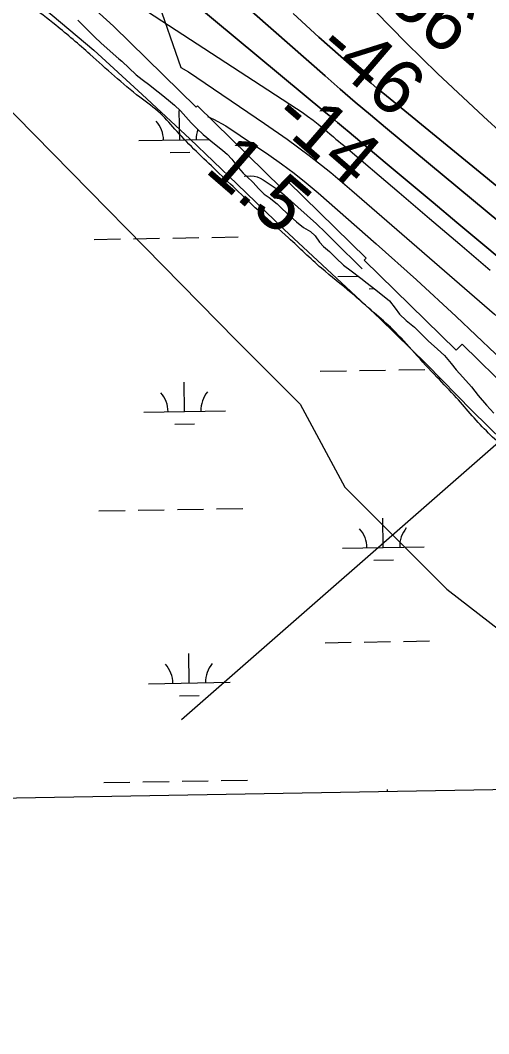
# Model space of a CAD drawing. Extents: x 3892998 to 3931244, y 278583 to 304547.
# Drawn here: x 3913942 to 3914515, y 284015 to 285257 of the extents above; entities that cross this region are included whole.
import ezdxf

# ---------------------------------------------------------------- set-up
doc = ezdxf.new("R2010")
doc.units = 0
for name, color, linetype in [('V-GRID-FRAM', 7, 'Continuous'), ('V-RIVR-EDGE', 7, 'Continuous'), ('V-RIVR-RANG', 7, 'Continuous'), ('V-RRAP-FSHR', 7, 'Continuous'), ('V-RRAP-RVMT', 7, 'Continuous'), ('V-SITE-VEGE', 7, 'Continuous'), ('V-TOPO-DPTH', 7, 'Continuous'), ('V-TOPO-MAJR', 7, 'Continuous'), ('V-TOPO-MINR', 7, 'Continuous'), ('V-TOPO-WATR', 7, 'Continuous'), ('V-WETL-SWMP', 7, 'Continuous')]:
    doc.layers.add(name, color=color, linetype=linetype)

msp = doc.modelspace()

# ---------------------------------------------------------------- linework, layer by layer
at = {"layer": 'V-GRID-FRAM'}
msp.add_lwpolyline([(3896958.4, 302195.2), (3928823.6, 302746.7), (3929146.3, 284567.1), (3897265.1, 284015.2), (3896958.4, 302195.2)], dxfattribs=at)
at = {"layer": 'V-RIVR-EDGE'}
msp.add_spline([(3914993.8, 284322.8), (3914968.3, 284342.8), (3914920.3, 284384.2), (3914880.1, 284418.3), (3914821, 284468.4), (3914766.3, 284522), (3914701.3, 284583.8), (3914632.5, 284646.6), (3914610.2, 284666.6), (3914581.2, 284690), (3914556, 284713.8), (3914514.8, 284750.9), (3914475.6, 284794.2), (3914451.8, 284819.5), (3914424.2, 284849.2), (3914397.6, 284877.9), (3914374.8, 284898.3), (3914346.7, 284922.7), (3914310.3, 284952.9), (3914270.1, 284989.9), (3914236.2, 285020.6), (3914181.9, 285072.2), (3914133.5, 285120.4), (3914113.2, 285142.3), (3914088, 285162.3), (3914026.9, 285214.9), (3913985.2, 285250.4), (3913923.7, 285300.6), (3913885.4, 285338.6), (3913828.2, 285387.3), (3913773, 285434), (3913712.4, 285486.1), (3913642.6, 285542.2), (3913620.3, 285557.3), (3913592.7, 285572.4), (3913575.7, 285582.2), (3913557.7, 285592.9), (3913537.8, 285602.2), (3913513.1, 285610), (3913480.6, 285617.8), (3913452, 285625.7), (3913431.6, 285624.8), (3913416.5, 285623.3), (3913398.5, 285612.2), (3913380, 285595.7), (3913368.8, 285578.8), (3913361, 285558.9), (3913353.2, 285538.5), (3913346.8, 285528.8), (3913334.6, 285516.7), (3913321, 285502.7), (3913315.6, 285483.2), (3913310.2, 285462.9), (3913309.7, 285439.5), (3913307.1, 285396.3), (3913306.6, 285384.7), (3913313.4, 285371.6), (3913315.8, 285356.5), (3913316.7, 285340.9), (3913314.3, 285325.4), (3913310.3, 285313.3), (3913303, 285304.1), (3913292.8, 285303.6), (3913281.2, 285304.1), (3913270.5, 285307.6), (3913265.7, 285307.6), (3913263.2, 285304.2), (3913266.1, 285298.3), (3913272.4, 285295.4), (3913294.3, 285287.6), (3913301.5, 285287.6), (3913314.2, 285288), (3913321.9, 285287), (3913325.8, 285283.6), (3913329.7, 285280.7), (3913333.5, 285262.7), (3913334.5, 285242.3), (3913329, 285204.5), (3913324.1, 285171), (3913320.6, 285146.2), (3913319.1, 285121.9), (3913321, 285110.3), (3913321, 285095.7), (3913319.5, 285083.6), (3913315.1, 285061.2), (3913296, 285013.2), (3913271.1, 284963.7), (3913263.3, 284941.4), (3913260.8, 284917.1), (3913261.7, 284891.9), (3913265, 284860.3), (3913263.5, 284819)], degree=3, dxfattribs=at)
at = {"layer": 'V-RIVR-RANG'}
msp.add_line((3914138.9, 284400), (3915102.1, 285243.1), dxfattribs=at)
at = {"layer": 'V-RRAP-FSHR'}
msp.add_lwpolyline([(3913910.3, 285324), (3913970.6, 285271.5), (3914031.8, 285219.8), (3914090.7, 285165.8), (3914149.3, 285111.3), (3914207, 285055.9), (3914264.5, 285000.3), (3914323.2, 284945.9), (3914381.8, 284891.4), (3914438.9, 284835.5), (3914494.9, 284778.3), (3914551.9, 284722.2), (3914610.7, 284667.3), (3914668.9, 284613.7), (3914727.9, 284559.7), (3914786.2, 284504.2), (3914845.3, 284450.4), (3914906.8, 284399.2), (3914969.5, 284349.5)], dxfattribs=at)
at = {"layer": 'V-RRAP-RVMT'}
for p, q in [((3914055.6, 285249.4), (3913968.2, 285329.4)), ((3914157, 285150), (3914055.6, 285249.4)), ((3914158.6, 285151.6), (3914157, 285150)), ((3914261.5, 285050.7), (3914158.6, 285151.6)), ((3914269.5, 285058.8), (3914261.5, 285050.7)), ((3914364.9, 284965.2), (3914269.5, 285058.8)), ((3914362.6, 284962.9), (3914364.9, 284965.2)), ((3914475.1, 284852.4), (3914362.6, 284962.9)), ((3914482.5, 284859.9), (3914475.1, 284852.4)), ((3914588.9, 284755.5), (3914482.5, 284859.9))]:
    msp.add_line(p, q, dxfattribs=at)
at = {"layer": 'V-SITE-VEGE'}
for p, q in [((3913753.7, 285324.9), (3914206.3, 284864.3)), ((3914206.3, 284864.3), (3914284.3, 284786.2)), ((3914284.3, 284786.2), (3914338.9, 284684.7)), ((3914338.9, 284684.7), (3914463.8, 284559.8)), ((3914463.8, 284559.8), (3914674.5, 284395.9)), ((3914838.2, 284319.4), (3913226.8, 284291.5))]:
    msp.add_line(p, q, dxfattribs=at)
at = {"layer": 'V-TOPO-DPTH'}
msp.add_line((3914093.5, 285327.6), (3914138, 285198.6), dxfattribs=at)
for points in [[(3915362.5, 284328.5), (3915042.9, 284585.9), (3915025, 284600.3), (3915007.3, 284614.7), (3914989.5, 284629.2), (3914971.8, 284643.7), (3914847.8, 284745.4), (3914768.2, 284810.9), (3914688.7, 284876.4), (3914609.2, 284942.1), (3914529.9, 285007.9), (3914388.8, 285125.2), (3914370.2, 285140.7), (3914351.6, 285156.4), (3914333.3, 285172.3), (3914315, 285188.3), (3914118.6, 285361.1), (3914060.1, 285412.9), (3914001.9, 285464.9), (3913944, 285517.3), (3913886.3, 285570)], [(3915362.5, 284328.5), (3915042.9, 284585.9), (3915025, 284600.3), (3915007.3, 284614.7), (3914989.5, 284629.2), (3914971.8, 284643.7), (3914847.8, 284745.4), (3914768.2, 284810.9), (3914688.7, 284876.4), (3914609.2, 284942.1), (3914529.9, 285007.9), (3914388.8, 285125.2), (3914370.2, 285140.7), (3914351.6, 285156.4), (3914333.3, 285172.3), (3914315, 285188.3), (3914118.6, 285361.1), (3914060.1, 285412.9), (3914018.1, 285450.4)], [(3914018.1, 285450.4), (3914093.5, 285327.6), (3914122.5, 285304.2), (3914315.7, 285143.3), (3914322.9, 285137.3), (3914330, 285131.3), (3914337.2, 285125.3), (3914344.4, 285119.3), (3914388.5, 285082.3), (3914417.8, 285057.7), (3914447.1, 285033.2), (3914476.3, 285008.7), (3914505.6, 284984.2), (3914971.2, 284594.7), (3914977.3, 284589.6), (3914983.4, 284584.5), (3914989.5, 284579.4), (3914995.6, 284574.3), (3915054.8, 284524.2), (3915090.5, 284494), (3915126.2, 284463.8), (3915161.8, 284433.6), (3915197.5, 284403.4), (3915287.3, 284327.2)], [(3915287.3, 284327.2), (3915197.5, 284403.4), (3915161.8, 284433.6), (3915126.2, 284463.8), (3915090.5, 284494), (3915054.8, 284524.2), (3914995.6, 284574.3), (3914989.5, 284579.4), (3914983.4, 284584.5), (3914977.3, 284589.6), (3914971.2, 284594.7), (3914505.6, 284984.2), (3914476.3, 285008.7), (3914447.1, 285033.2), (3914417.8, 285057.7), (3914388.5, 285082.3), (3914344.4, 285119.3), (3914337.2, 285125.3), (3914330, 285131.3), (3914322.9, 285137.3), (3914315.7, 285143.3), (3914122.5, 285304.2), (3914093.5, 285327.6)], [(3914275.6, 285264.8), (3914307.1, 285235.9), (3914357.6, 285191.2), (3914364.4, 285185.2), (3914371.3, 285179.3), (3914378.3, 285173.4), (3914385.3, 285167.6), (3914903.1, 284743.7), (3914923.9, 284726.6), (3914944.8, 284709.6), (3914965.7, 284692.5), (3914986.6, 284675.5), (3915019.4, 284648.7), (3915023.9, 284645.1), (3915028.4, 284641.4), (3915032.9, 284637.8), (3915037.4, 284634.1), (3915111.1, 284574.5), (3915152.4, 284541), (3915193.7, 284507.5), (3915235, 284473.9), (3915276.2, 284440.4), (3915412.3, 284329.4)], [(3917760.4, 284370), (3915412.3, 284329.4), (3915276.2, 284440.4), (3915235, 284473.9), (3915193.7, 284507.5), (3915152.4, 284541), (3915111.1, 284574.5), (3915037.4, 284634.1), (3915032.9, 284637.8), (3915028.4, 284641.4), (3915023.9, 284645.1), (3915019.4, 284648.7), (3914986.6, 284675.5), (3914965.7, 284692.5), (3914944.8, 284709.6), (3914923.9, 284726.6), (3914903.1, 284743.7), (3914385.3, 285167.6), (3914378.3, 285173.4), (3914371.3, 285179.3), (3914364.4, 285185.2), (3914357.6, 285191.2), (3914307.1, 285235.9), (3914275.6, 285264.8)], [(3914138, 285198.6), (3914147.7, 285193.3), (3914240.8, 285130.2), (3914268.3, 285110.9), (3914295.4, 285090.8), (3914321.7, 285069.9), (3914347.5, 285048.2), (3914522.2, 284896.4), (3914591.8, 284835.1), (3914660.9, 284773.1), (3914729.2, 284710.2), (3914796.8, 284646.7), (3914882, 284565.6), (3914906.8, 284542.3), (3914931.8, 284519.1), (3914957, 284496.2), (3914982.3, 284473.5), (3915042.1, 284420.6), (3915097.8, 284372), (3915152.9, 284324.9)]]:
    msp.add_lwpolyline(points, dxfattribs=at)
at = {"layer": 'V-TOPO-MAJR'}
msp.add_lwpolyline([(3914376.7, 285267.3), (3914395.2, 285247.9), (3914413.9, 285228.7), (3914433.1, 285210), (3914452.5, 285191.4), (3914508.9, 285138.7), (3914557, 285094.4), (3914605.7, 285050.7), (3914655.2, 285007.9), (3914705.2, 284965.7), (3915030.9, 284695.6), (3915043, 284685.4), (3915055.2, 284675.3), (3915067.4, 284665.2), (3915079.5, 284655.1), (3915208.4, 284547.3), (3915285.1, 284483.3), (3915361.8, 284419.4), (3915438.5, 284355.5)], dxfattribs=at)
at = {"layer": 'V-TOPO-MINR'}
for points in [[(3913886.3, 285570), (3913944, 285517.3), (3914001.9, 285464.9), (3914060.1, 285412.9), (3914118.6, 285361.1), (3914315, 285188.3), (3914333.3, 285172.3), (3914351.6, 285156.4), (3914370.2, 285140.7), (3914388.8, 285125.2), (3914529.9, 285007.9), (3914609.2, 284942.1), (3914688.7, 284876.4), (3914768.2, 284810.9), (3914847.8, 284745.4), (3914971.8, 284643.7), (3914989.5, 284629.2), (3915007.3, 284614.7), (3915025, 284600.3), (3915042.9, 284585.9), (3915362.5, 284328.5)], [(3914093.5, 285327.6), (3914122.5, 285304.2), (3914315.7, 285143.3), (3914322.9, 285137.3), (3914330, 285131.3), (3914337.2, 285125.3), (3914344.4, 285119.3), (3914388.5, 285082.3), (3914417.8, 285057.7), (3914447.1, 285033.2), (3914476.3, 285008.7), (3914505.6, 284984.2), (3914971.2, 284594.7), (3914977.3, 284589.6), (3914983.4, 284584.5), (3914989.5, 284579.4), (3914995.6, 284574.3), (3915054.8, 284524.2), (3915090.5, 284494), (3915126.2, 284463.8), (3915161.8, 284433.6), (3915197.5, 284403.4), (3915287.3, 284327.2)], [(3914097.2, 285267.2), (3914279.9, 285148.5), (3914286.7, 285143.9), (3914293.4, 285139.1), (3914300, 285134.2), (3914306.4, 285129.1), (3914317.6, 285119.9), (3914320.6, 285117.4), (3914325.1, 285113.6), (3914328.1, 285111), (3914331.2, 285108.5), (3914334.2, 285106), (3914337.2, 285103.4), (3914405.5, 285045.5), (3914442.7, 285013.9), (3914479.8, 284982.3), (3914516.8, 284950.5)], [(3914275.6, 285264.8), (3914307.1, 285235.9), (3914357.6, 285191.2), (3914364.4, 285185.2), (3914371.3, 285179.3), (3914378.3, 285173.4), (3914385.3, 285167.6), (3914903.1, 284743.7), (3914923.9, 284726.6), (3914944.8, 284709.6), (3914965.7, 284692.5), (3914986.6, 284675.5), (3915019.4, 284648.7), (3915023.9, 284645.1), (3915028.4, 284641.4), (3915032.9, 284637.8), (3915037.4, 284634.1), (3915111.1, 284574.5), (3915152.4, 284541), (3915193.7, 284507.5), (3915235, 284473.9), (3915276.2, 284440.4), (3915412.3, 284329.4)], [(3914138, 285198.6), (3914147.7, 285193.3), (3914240.8, 285130.2), (3914268.3, 285110.9), (3914295.4, 285090.8), (3914321.7, 285069.9), (3914347.5, 285048.2), (3914522.2, 284896.4), (3914591.8, 284835.1), (3914660.9, 284773.1), (3914729.2, 284710.2), (3914796.8, 284646.7), (3914882, 284565.6), (3914906.8, 284542.3), (3914931.8, 284519.1), (3914957, 284496.2), (3914982.3, 284473.5), (3915042.1, 284420.6), (3915097.8, 284372), (3915152.9, 284324.9)], [(3914171, 285138.5), (3914178.1, 285135.6), (3914193.3, 285127.3), (3914245.9, 285091.6), (3914261.5, 285080.7), (3914276.8, 285069.3), (3914291.6, 285057.4), (3914306.2, 285045.1), (3914377.2, 284982.8), (3914426.6, 284938.6), (3914475.4, 284893.8), (3914523.3, 284848), (3914570.6, 284801.6), (3914715.4, 284656.7)]]:
    msp.add_lwpolyline(points, dxfattribs=at)
at = {"layer": 'V-TOPO-WATR'}
msp.add_lwpolyline([(3914215.6, 285065.7), (3914223.8, 285065.8), (3914227.8, 285065.5), (3914231.7, 285064.7), (3914235.4, 285063.2), (3914238.9, 285061.3), (3914251.1, 285053), (3914254.7, 285050.5), (3914258.2, 285047.8), (3914261.7, 285045.1), (3914265.1, 285042.2), (3914281.5, 285027.8), (3914293, 285017.5), (3914304.3, 285007.1), (3914315.4, 284996.5), (3914326.4, 284985.7), (3914360, 284952.1)], dxfattribs=at)
at = {"layer": 'V-WETL-SWMP'}
for p, q in [((3914012, 285256.5), (3914018.8, 285249.7)), ((3914018.8, 285249.7), (3914025, 285243.5)), ((3914025, 285243.5), (3914032.4, 285236.2)), ((3914032.4, 285236.2), (3914040.6, 285228.6)), ((3914040.6, 285228.6), (3914062.1, 285209.2)), ((3914062.1, 285209.2), (3914065.8, 285206.3)), ((3914065.8, 285206.3), (3914083.6, 285189.7)), ((3914083.6, 285189.7), (3914091, 285183.9)), ((3914091, 285183.9), (3914100.2, 285177)), ((3914100.2, 285177), (3914106.8, 285171.8)), ((3914106.8, 285171.8), (3914114.2, 285166.2)), ((3914114.2, 285166.2), (3914123.2, 285158.6)), ((3914123.2, 285158.6), (3914130.4, 285152.4)), ((3914130.4, 285152.4), (3914137.6, 285145.6)), ((3914136.9, 285110.1), (3914136.3, 285146)), ((3914137.6, 285145.6), (3914144.4, 285138.2)), ((3914144.4, 285138.2), (3914151, 285130.8)), ((3914151, 285130.8), (3914157.8, 285123.8)), ((3914157.8, 285123.8), (3914165.4, 285116.6)), ((3914165.4, 285116.6), (3914170, 285112.8)), ((3914086.9, 285109.2), (3914172.7, 285110.7)), ((3914170, 285112.8), (3914177.4, 285107)), ((3914177.4, 285107), (3914183.2, 285102.2)), ((3914125.2, 285094.4), (3914149.2, 285094.8)), ((3914183.2, 285102.2), (3914189.4, 285097.2)), ((3914189.4, 285097.2), (3914194.8, 285092.6)), ((3914194.8, 285092.6), (3914200.8, 285086.4)), ((3914200.8, 285086.4), (3914205.4, 285079.8)), ((3914205.4, 285079.8), (3914208.8, 285075.6)), ((3914208.8, 285075.6), (3914214.6, 285069.4)), ((3914214.6, 285069.4), (3914218.8, 285065.2)), ((3914218.8, 285065.2), (3914226.7, 285057.8)), ((3914226.7, 285057.8), (3914233.3, 285050.4)), ((3914233.3, 285050.4), (3914240.3, 285043.6)), ((3914240.3, 285043.6), (3914246.5, 285039.4)), ((3914246.5, 285039.4), (3914256.3, 285031.6)), ((3914256.3, 285031.6), (3914262.7, 285025.2)), ((3914262.7, 285025.2), (3914271.1, 285017.4)), ((3914271.1, 285017.4), (3914279.7, 285009.8)), ((3914279.7, 285009.8), (3914288.5, 285002.8)), ((3914288.5, 285002.8), (3914297.1, 284997.8)), ((3914297.1, 284997.8), (3914302.5, 284992.4)), ((3914302.5, 284992.4), (3914307.9, 284984.8)), ((3914032.2, 284988.2), (3914064.2, 284988.7)), ((3914080.2, 284989), (3914112.2, 284989.5)), ((3914128.2, 284989.8), (3914160.2, 284990.4)), ((3914176.2, 284990.6), (3914208.2, 284991.2)), ((3914307.9, 284984.8), (3914312.9, 284979.4)), ((3914312.9, 284979.4), (3914320.3, 284973.4)), ((3914320.3, 284973.4), (3914328.5, 284965.3)), ((3914328.5, 284965.3), (3914337.3, 284956.7)), ((3914337.3, 284956.7), (3914346.9, 284949.5)), ((3914330.3, 284942.6), (3914355.2, 284943)), ((3914346.9, 284949.5), (3914358.5, 284940.5)), ((3914358.5, 284940.5), (3914366.3, 284934.7)), ((3914366.3, 284934.7), (3914375.3, 284927.5)), ((3914368.6, 284927.8), (3914374.8, 284927.9)), ((3914375.3, 284927.5), (3914382.9, 284921.3)), ((3914382.9, 284921.3), (3914393.5, 284912.7)), ((3914393.5, 284912.7), (3914400.5, 284904.1)), ((3914400.5, 284904.1), (3914405.9, 284896.7)), ((3914405.9, 284896.7), (3914414.1, 284888.7)), ((3914414.1, 284888.7), (3914424.1, 284880.7)), ((3914424.1, 284880.7), (3914433.1, 284871.7)), ((3914433.1, 284871.7), (3914440.9, 284863.9)), ((3914440.9, 284863.9), (3914452.5, 284853.7)), ((3914452.5, 284853.7), (3914460.9, 284845.9)), ((3914460.9, 284845.9), (3914469.2, 284836.3)), ((3914469.2, 284836.3), (3914475.2, 284828.5)), ((3914308.9, 284826.7), (3914340.9, 284827.3)), ((3914356.9, 284827.6), (3914388.9, 284828.1)), ((3914404.9, 284828.4), (3914436.9, 284829)), ((3914475.2, 284828.5), (3914483.6, 284819.5)), ((3914483.6, 284819.5), (3914494.2, 284807.5)), ((3914142.7, 284777.4), (3914142.1, 284813.4)), ((3914494.2, 284807.5), (3914502.4, 284796.9)), ((3914502.4, 284796.9), (3914512.6, 284785.3)), ((3914512.6, 284785.3), (3914521.4, 284775.3)), ((3914092.7, 284776.6), (3914192.7, 284778.3)), ((3914131, 284761.8), (3914155, 284762.2)), ((3914037.9, 284655.5), (3914069.9, 284656.1)), ((3914085.9, 284656.4), (3914117.9, 284656.9)), ((3914133.9, 284657.2), (3914165.9, 284657.7)), ((3914181.9, 284658), (3914213.9, 284658.6)), ((3914386.1, 284610.8), (3914385.5, 284646.8)), ((3914336.1, 284609.9), (3914436.1, 284611.7)), ((3914374.4, 284595.2), (3914398.4, 284595.6)), ((3914362.7, 284494.9), (3914394.7, 284495.5)), ((3914410.7, 284495.8), (3914442.7, 284496.3)), ((3914314.7, 284494.1), (3914346.7, 284494.7)), ((3914148.5, 284444.8), (3914147.8, 284480.8)), ((3914098.5, 284443.9), (3914198.4, 284445.7)), ((3914136.7, 284429.2), (3914160.7, 284429.6)), ((3915020.6, 284322.6), (3913193.8, 284291)), ((3914043.7, 284322.9), (3914075.7, 284323.5)), ((3914091.7, 284323.7), (3914123.7, 284324.3)), ((3914139.7, 284324.6), (3914171.7, 284325.1)), ((3914187.7, 284325.4), (3914219.7, 284325.9)), ((3914391.3, 284311.7), (3914391.2, 284314.2))]:
    msp.add_line(p, q, dxfattribs=at)
for centre, start, end in [((3914081.7, 285109.6), 0.2199, 41.7635), ((3914192.2, 285111.5), 161.181, 181.7635), ((3914087.4, 284776.9), 0.2199, 41.7635), ((3914197.9, 284778.9), 140.2199, 181.7635), ((3914330.8, 284610.3), 0.2199, 41.7635), ((3914441.3, 284612.2), 140.2199, 181.7635), ((3914093.2, 284444.3), 0.2199, 41.7635), ((3914203.7, 284446.2), 140.2199, 181.7635)]:
    msp.add_arc(centre, 35.2, start, end, dxfattribs=at)

# ---------------------------------------------------------------- texts
at = {"layer": 'V-RIVR-RANG'}
for s, rotation, p in [('-56', 319.4396, (3914365.4, 285295.7)), ('-46', 319.4396, (3914301.8, 285218.5)), ('-14', 319.1583, (3914247.3, 285133.9)), ('1.5', 319.1583, (3914166.1, 285071.9))]:
    msp.add_text(s, height=67, rotation=rotation, dxfattribs=at).set_placement(p)

doc.saveas('drawing.dxf')
